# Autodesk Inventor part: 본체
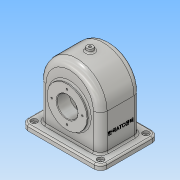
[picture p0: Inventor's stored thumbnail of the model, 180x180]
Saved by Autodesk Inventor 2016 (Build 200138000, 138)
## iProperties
Created: 2018-08
Part Number: 본체
Material: 알루미늄 6061
Document SubType Name: Modeling
Designer: Administrator
Density: 2.7 g/cm^3
Appearance: 알루미늄 - 평지
Mass: 1091.81 g
Surface Area: 1181.2 cm^2
Volume: 404.373 cm^3
Author: Administrator
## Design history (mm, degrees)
sketch "스케치1"
  geometry: L1 (-75, 55)-(75, 55); L2 (75, 55)-(75, -55); L3 (75, -55)-(-75, -55); L4 (-75, -55)-(-75, 55); L5 (-75, 55)-(75, -55); L6 (75, 55)-(-75, -55); 1 further point
  constraints: 12 end point, 2 midpoint, 2 parallel, 1 horizontal, 1 perpendicular
  dimensions: "d0" = 150 distance of L2.end L3.end; "d1" = 110 distance of L1.end L2.end
extrude "돌출1" new body sketch "스케치1" distance "d2" = 10; taper "d3" = 0 deg
sketch "스케치2"
  geometry: L1 (-75, 0)-(75, 0) reference; L2 (75, 10)-(-75, 10) reference; L3 (58, 78)-(58, 10); L4 (-58, 78)-(-58, 10); A1 r 58 centre (0, 78) between (58, 78) and (-58, 78); 2 further points
  constraints: 4 end point, 2 point on circle, 2 point on line, 2 tangent, 1 centre point, 1 midpoint, 1 perpendicular, 1 vertical, 1 vertical alignment
  dimensions: "d4" = 58 radius of A1; "d5" = 78 distance from line of L1 A1.centre
extrude "돌출2" join sketch "스케치2" stored distance "d6" = 77; taper "d7" = 0 deg
feature "쉘1" dims "d8" = 10, "d9" = 6, "d10" = 5
sketch "스케치5"
  geometry: L1 (75, 0)-(-75, 0) reference; C1 r 38 at (0, 65); 2 further points
  constraints: 1 centre point, 1 midpoint, 1 vertical alignment
  dimensions: "d11" = 76 diameter of C1; "d12" = 65 distance from line of L1 C1.centre
extrude "돌출3" join sketch "스케치5" distance "d13" = 5; taper "d14" = 0 deg
sketch "스케치6"
  geometry: C1 r 38 at (0, -65) reference; C2 r 38 at (0, -65); 1 further point
  constraints: 1 centre point, 1 coincident
  dimensions: "d15" = 76 diameter of C2
extrude "돌출4" join sketch "스케치6" distance "d16" = 10; taper "d17" = 0 deg
sketch "스케치7"
  geometry: L1 (-52.254, 65)-(63.994, 65); L2 (-55, 0)-(55, 0) reference; L3 (-33.5, 130)-(-33.5, 78) reference; L4 (33.5, 78)-(33.5, 130) reference; L5 (-33.5, 104.747)-(-19.5, 93); L6 (-19.5, 93)-(-19.5, 65); L7 (-33.5, 104.747)-(-33.5, 65); L8 (-33.5, 78)-(-33.5, 0) reference; L9 (-43.5, 103)-(-43.5, 27) reference; 1 further point
  constraints: 8 end point, 4 point on line, 1 horizontal, 1 perpendicular
  dimensions: "d18" = 65 distance between parallel lines of L2 L1; "d19" = 56 diameter of L5.end L1; "d20" = 50 deg angle of L6 L5; "d21" = 24 distance between parallel lines of L9 L6
revolve "회전1" sketch "스케치7" stored, may be unused: angle "d22" = 90 deg
sketch "스케치9"
  geometry: C1 r 38 at (0, 0) reference; C2 r 20 at (0, 0); 1 further point
  constraints: 1 centre point, 1 coincident
  dimensions: "d23" = 40 diameter of C2
extrude "돌출5" cut sketch "스케치9" stored distance "d24" = 10; taper "d25" = 0 deg
node "작업 평면1"
sketch "스케치10"
  geometry: C1 r 6 at (0, 0); 1 further point
  constraints: 1 centre point, 1 coincident
  dimensions: "d27" = 12 diameter of C1
extrude "돌출6" join sketch "스케치10" stored distance "d28" = 10; taper "d29" = 0 deg
sketch "스케치11" dims "d30" = 58
  geometry: C1 r 20 at (0, 0) reference; 3 further points
  constraints: 2 vertical alignment, 1 coincident, 2 other
hole "구멍1" sketch "스케치11" at (0, 29) diameter "d31" = 3.242; stored, may be unused: countersink angle "d35" = 90 deg, drill point angle "d37" = 118 deg; dims "d32" = 8, "d33" = 4, "d34" = 2, "d36" = 10
sketch "스케치12" dims "d41" = 58
  geometry: C1 r 20 at (0, 0) reference; C2 r 38 at (0, 0) reference; 3 further points
  constraints: 2 vertical alignment, 1 coincident, 2 other
hole "구멍2" sketch "스케치12" at (0, -29) diameter "d42" = 3.242; stored, may be unused: countersink angle "d46" = 90 deg, drill point angle "d48" = 118 deg; dims "d43" = 8, "d44" = 4, "d45" = 2, "d47" = 10
hole "구멍3" diameter "d54" = 4.459; stored, may be unused: countersink angle "d58" = 90 deg, drill point angle "d60" = 118 deg; dims "d55" = 20, "d56" = 4, "d57" = 2, "d59" = 12.8, "d86" = 10, "d87" = 10
fillet "모깎기1" dims "d61" = 12
fillet "모깎기2" dims "d62" = 13
fillet "모깎기3" dims "d63" = 8
fillet "모깎기4" dims "d64" = 3
chamfer "모따기1" distance "d65" = 1; stored, may be unused: second distance "d66" = 2, angle "d67" = 45 deg
chamfer "모따기2" distance "d68" = 1; stored, may be unused: second distance "d69" = 2, angle "d70" = 45 deg
sketch "스케치13"
  geometry: C1 r 6 at (63, 43); A1 r 9 centre (63, 43) between (72, 43) and (63, 52) reference; 1 further point
  constraints: 1 centre point, 1 coincident
  dimensions: "d71" = 12 diameter of C1
extrude "돌출7" cut sketch "스케치13" distance "d72" = 4; taper "d73" = 0 deg
sketch "스케치14"
  geometry: C1 r 6 at (0, 0) reference; C2 r 2.5 at (0, 0); 1 further point
  constraints: 1 centre point, 1 coincident
  dimensions: "d74" = 5 diameter of C2
extrude "돌출8" cut sketch "스케치14" stored distance "d75" = 0; taper "d76" = 0 deg
feature "면 기울기1" dims angle "d77" = 5 deg
fillet "모깎기5" dims "d78" = 3
sketch "스케치15"
  geometry: L1 (78, 68.5)-(78, -17.5) reference; L2 (0, -13)-(68, -13) reference; 2 further points
  constraints: 1 other
  dimensions: "d79" = 40 distance from line of L1 point (38, 25.5); "d80" = 38.5 distance from line of L2 point (38, 25.5)
fillet "모깎기6" dims "d81" = 3
feature "엠보싱1" dims "d82" = 0.5, "d83" = 0
sketch "스케치16"
  geometry: L1 (-98.055, 171.263)-(93.151, 171.263); L2 (93.151, 171.263)-(93.151, -34.452); L3 (93.151, -34.452)-(-98.055, -34.452); L4 (-98.055, -34.452)-(-98.055, 171.263); 1 further point
  constraints: 8 end point, 2 parallel, 1 horizontal, 1 perpendicular
extrude "돌출9" cut sketch "스케치16" stored distance "d84" = 4; taper "d85" = 0 deg
node "솔리드1"
pattern_circular "원형 패턴1" dims angle "d39" = 360 deg
pattern_circular "원형 패턴2" dims angle "d50" = 360 deg
mirror "대칭1"
mirror "대칭2"
node "투영된 루프1"
node "투영된 루프2"
other parameters: "d26" = 142
